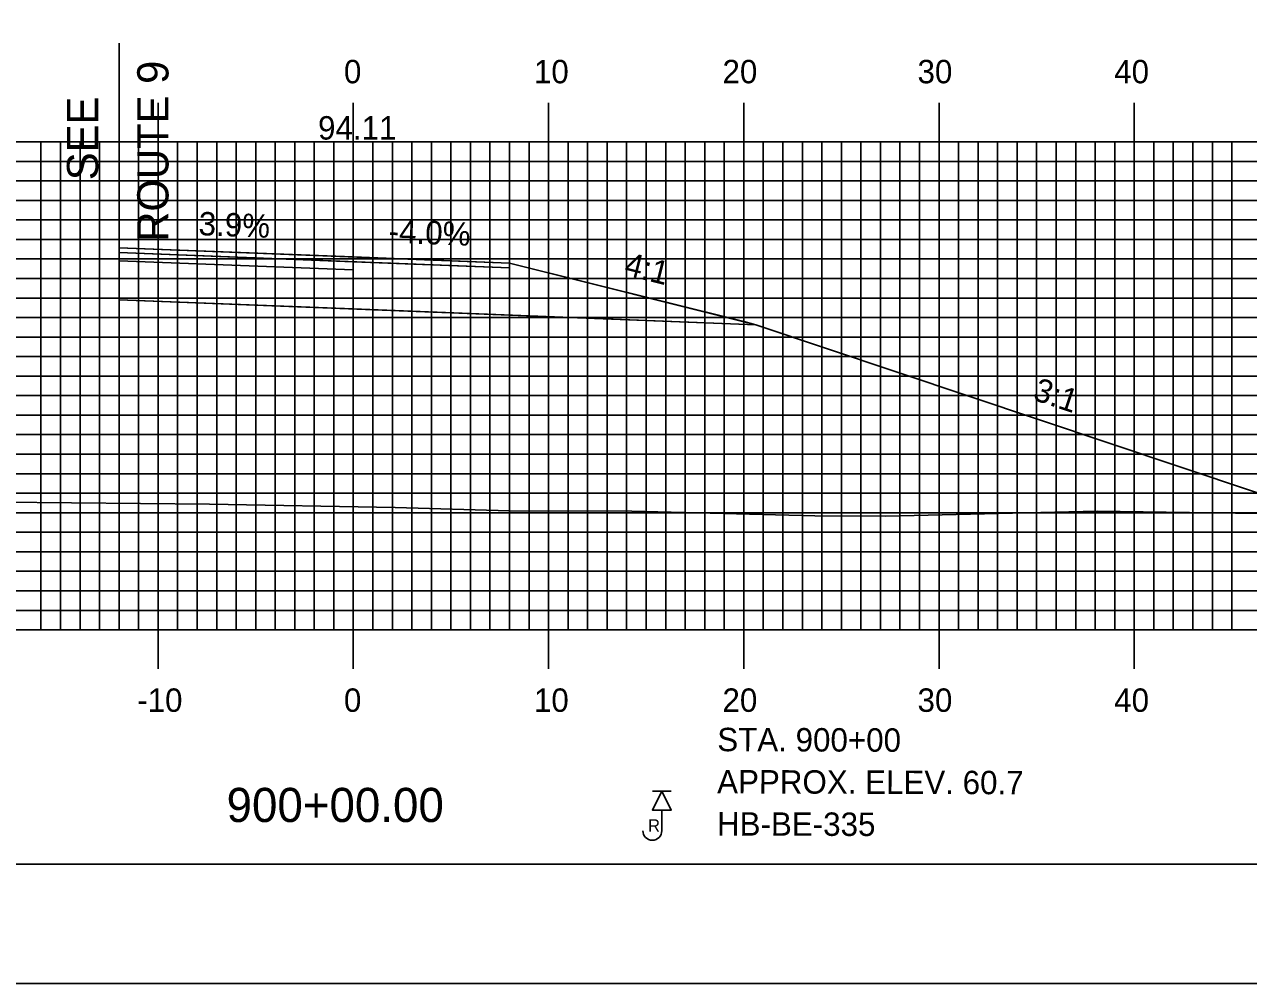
# Model space of a CAD drawing. Extents: x 856323 to 856666, y 364765 to 364985.
# Drawn here: x 856471.9 to 856534.6, y 364765.2 to 364814.3 of the extents above; entities that cross this region are included whole.
import ezdxf

# ---------------------------------------------------------------- set-up
doc = ezdxf.new("R2010")
doc.units = 0
for name, color, linetype in [('ANNOTATION', 7, 'Continuous'), ('BORDER', 7, 'Continuous'), ('BORING - REFUSAL', 7, 'Continuous'), ('D_Roadway_Centerline', 7, 'Continuous'), ('D_Roadway_Centerline_Text', 7, 'Continuous'), ('D_Roadway_Edge_Shoulder', 7, 'Continuous'), ('D_Roadway_Edge_TW', 7, 'Continuous'), ('D_Roadway_Pavement', 7, 'Continuous'), ('D_Roadway_SlopeLines', 7, 'Continuous'), ('D_Roadway_SubGrade', 7, 'Continuous'), ('H_V ANNOTATION', 7, 'Continuous'), ('MAJOR', 7, 'Continuous'), ('MINOR', 7, 'Continuous'), ('PLOT BOUNDARY', 7, 'Continuous'), ('S_Roadway_Centerline', 7, 'Continuous')]:
    doc.layers.add(name, color=color, linetype=linetype)

msp = doc.modelspace()

# ---------------------------------------------------------------- linework, layer by layer
at = {"layer": 'BORDER'}
msp.add_lwpolyline([(856339.168, 364771.302), (856659.168, 364771.302), (856659.168, 364981.302), (856339.168, 364981.302)], close=True, dxfattribs=at)
at = {"layer": 'BORING - REFUSAL'}
for p, q in [((856505.048, 364775.03), (856504.089, 364775.03)), ((856504.568, 364774.07), (856504.568, 364773.011))]:
    msp.add_line(p, q, dxfattribs=at)
msp.add_lwpolyline([(856504.568, 364775.03), (856505.048, 364774.07), (856504.089, 364774.07)], close=True, dxfattribs=at)
msp.add_arc((856504.083, 364773.011), 0.485, 180, 0, dxfattribs=at)
at = {"layer": 'D_Roadway_Centerline'}
msp.add_lwpolyline([(856476.768, 364802.881), (856476.768, 364802.881), (856488.768, 364802.411), (856496.768, 364802.091), (856508.768, 364799.091), (856509.389, 364798.935), (856538.439, 364789.201), (856538.441, 364789.2)], dxfattribs=at)
at = {"layer": 'D_Roadway_Edge_Shoulder'}
for points in [[(856476.768, 364802.881), (856496.768, 364802.091), (856496.768, 364801.841), (856476.768, 364802.631)], [(856476.768, 364802.881), (856496.768, 364802.091), (856496.768, 364801.841), (856476.768, 364802.631)], [(856476.768, 364802.881), (856496.768, 364802.091), (856496.768, 364801.841), (856476.768, 364802.631)], [(856476.768, 364802.881), (856496.768, 364802.091), (856496.768, 364801.841), (856476.768, 364802.631)], [(856476.768, 364802.881), (856496.768, 364802.091), (856496.768, 364801.841), (856476.768, 364802.631)], [(856476.768, 364802.881), (856496.768, 364802.091), (856496.768, 364801.841), (856476.768, 364802.631)], [(856488.768, 364802.411), (856496.768, 364802.091), (856496.768, 364801.841), (856488.768, 364802.161)]]:
    msp.add_lwpolyline(points, close=True, dxfattribs=at)
at = {"layer": 'D_Roadway_Edge_TW'}
msp.add_lwpolyline([(856476.768, 364802.881), (856476.768, 364802.631)], dxfattribs=at)
msp.add_lwpolyline([(856476.768, 364802.881), (856488.768, 364802.411), (856488.768, 364802.161), (856476.768, 364802.631)], close=True, dxfattribs=at)
msp.add_lwpolyline([(856476.768, 364802.881), (856488.768, 364802.411), (856488.768, 364802.161), (856476.768, 364802.631)], close=True, dxfattribs=at)
at = {"layer": 'D_Roadway_Pavement'}
msp.add_lwpolyline([(856476.768, 364802.631), (856488.768, 364802.161), (856488.768, 364801.744), (856476.768, 364802.214)], close=True, dxfattribs=at)
msp.add_lwpolyline([(856476.768, 364802.631), (856488.768, 364802.161), (856488.768, 364801.744), (856476.768, 364802.214)], close=True, dxfattribs=at)
for points in [[(856476.768, 364802.631), (856476.768, 364802.214)], [(856476.768, 364802.631), (856476.768, 364802.214)], [(856476.768, 364802.631), (856476.768, 364802.214)], [(856476.768, 364802.631), (856476.768, 364802.214)], [(856476.768, 364802.631), (856476.768, 364802.214)], [(856476.768, 364802.631), (856476.768, 364802.214)], [(856476.768, 364802.631), (856476.768, 364802.214)], [(856488.768, 364802.161), (856488.768, 364801.744)], [(856488.768, 364802.161), (856488.768, 364801.744)], [(856488.768, 364802.161), (856488.768, 364801.744)], [(856488.768, 364802.161), (856488.768, 364801.744)], [(856488.768, 364802.161), (856488.768, 364801.744)], [(856488.768, 364802.161), (856488.768, 364801.744)], [(856488.768, 364802.161), (856488.768, 364801.744)], [(856488.768, 364802.161), (856488.768, 364801.744)]]:
    msp.add_lwpolyline(points, dxfattribs=at)
at = {"layer": 'D_Roadway_SlopeLines'}
msp.add_lwpolyline([(856496.768, 364802.091), (856509.389, 364798.935), (856538.441, 364789.2)], dxfattribs=at)
at = {"layer": 'D_Roadway_SubGrade'}
msp.add_line((856476.768, 364813.354), (856476.768, 364800.214), dxfattribs=at)
for points in [[(856476.768, 364800.214), (856509.389, 364798.935), (856496.768, 364802.091), (856496.768, 364801.841), (856476.768, 364802.631)], [(856476.768, 364802.214), (856476.768, 364802.631), (856496.768, 364801.841), (856496.768, 364802.091), (856509.389, 364798.935), (856476.768, 364800.214)], [(856476.768, 364802.214), (856476.768, 364802.631), (856496.768, 364801.841), (856496.768, 364802.091), (856509.389, 364798.935), (856476.768, 364800.214)], [(856476.768, 364802.214), (856476.768, 364802.631), (856496.768, 364801.841), (856496.768, 364802.091), (856509.389, 364798.935), (856476.768, 364800.214)], [(856476.768, 364802.214), (856476.768, 364802.631), (856496.768, 364801.841), (856496.768, 364802.091), (856509.389, 364798.935), (856476.768, 364800.214)], [(856476.768, 364802.214), (856476.768, 364802.631), (856496.768, 364801.841), (856496.768, 364802.091), (856509.389, 364798.935), (856476.768, 364800.214)], [(856496.768, 364801.841), (856476.768, 364802.631), (856476.768, 364802.214), (856476.768, 364800.214), (856509.389, 364798.935), (856496.768, 364802.091)], [(856496.768, 364801.841), (856476.768, 364802.631), (856476.768, 364802.214), (856476.768, 364800.214), (856509.389, 364798.935), (856496.768, 364802.091)], [(856476.768, 364802.214), (856488.768, 364801.744), (856488.768, 364799.744), (856476.768, 364800.214)], [(856476.768, 364802.214), (856488.768, 364801.744), (856488.768, 364799.744), (856476.768, 364800.214)], [(856488.768, 364801.744), (856488.768, 364802.161), (856496.768, 364801.841), (856496.768, 364802.091), (856509.389, 364798.935), (856488.768, 364799.744)], [(856488.768, 364801.744), (856488.768, 364802.161), (856496.768, 364801.841), (856496.768, 364802.091), (856509.389, 364798.935), (856488.768, 364799.744)], [(856488.768, 364799.744), (856509.389, 364798.935), (856496.768, 364802.091), (856496.768, 364801.841), (856488.768, 364802.161), (856488.768, 364801.744)]]:
    msp.add_lwpolyline(points, close=True, dxfattribs=at)
msp.add_lwpolyline([(856476.768, 364802.214), (856476.768, 364800.214)], dxfattribs=at)
at = {"layer": 'MAJOR'}
for p, q in [((856478.768, 364810.306), (856478.768, 364808.302)), ((856488.768, 364810.306), (856488.768, 364808.302)), ((856498.768, 364810.306), (856498.768, 364808.302)), ((856508.768, 364810.306), (856508.768, 364808.302)), ((856518.768, 364810.306), (856518.768, 364808.302)), ((856528.768, 364810.306), (856528.768, 364808.302)), ((856348.768, 364808.302), (856628.768, 364808.302)), ((856348.768, 364808.302), (856628.768, 364808.302)), ((856478.768, 364783.302), (856478.768, 364808.302)), ((856488.768, 364783.302), (856488.768, 364808.302)), ((856498.768, 364783.302), (856498.768, 364808.302)), ((856508.768, 364783.302), (856508.768, 364808.302)), ((856518.768, 364783.302), (856518.768, 364808.302)), ((856528.768, 364783.302), (856528.768, 364808.302)), ((856348.768, 364803.302), (856628.768, 364803.302)), ((856348.768, 364798.302), (856628.768, 364798.302)), ((856348.768, 364793.302), (856628.768, 364793.302)), ((856348.768, 364788.302), (856628.768, 364788.302)), ((856348.768, 364783.302), (856628.768, 364783.302)), ((856348.768, 364783.302), (856628.768, 364783.302)), ((856478.768, 364781.298), (856478.768, 364783.302)), ((856488.768, 364781.298), (856488.768, 364783.302)), ((856498.768, 364781.298), (856498.768, 364783.302)), ((856508.768, 364781.298), (856508.768, 364783.302)), ((856518.768, 364781.298), (856518.768, 364783.302)), ((856528.768, 364781.298), (856528.768, 364783.302))]:
    msp.add_line(p, q, dxfattribs=at)
at = {"layer": 'MINOR'}
for p, q in [((856472.768, 364783.302), (856472.768, 364808.302)), ((856473.768, 364783.302), (856473.768, 364808.302)), ((856474.768, 364783.302), (856474.768, 364808.302)), ((856475.768, 364783.302), (856475.768, 364808.302)), ((856476.768, 364783.302), (856476.768, 364808.302)), ((856477.768, 364783.302), (856477.768, 364808.302)), ((856479.768, 364783.302), (856479.768, 364808.302)), ((856480.768, 364783.302), (856480.768, 364808.302)), ((856481.768, 364783.302), (856481.768, 364808.302)), ((856482.768, 364783.302), (856482.768, 364808.302)), ((856483.768, 364783.302), (856483.768, 364808.302)), ((856484.768, 364783.302), (856484.768, 364808.302)), ((856485.768, 364783.302), (856485.768, 364808.302)), ((856486.768, 364783.302), (856486.768, 364808.302)), ((856487.768, 364783.302), (856487.768, 364808.302)), ((856489.768, 364783.302), (856489.768, 364808.302)), ((856490.768, 364783.302), (856490.768, 364808.302)), ((856491.768, 364783.302), (856491.768, 364808.302)), ((856492.768, 364783.302), (856492.768, 364808.302)), ((856493.768, 364783.302), (856493.768, 364808.302)), ((856494.768, 364783.302), (856494.768, 364808.302)), ((856495.768, 364783.302), (856495.768, 364808.302)), ((856496.768, 364783.302), (856496.768, 364808.302)), ((856497.768, 364783.302), (856497.768, 364808.302)), ((856499.768, 364783.302), (856499.768, 364808.302)), ((856500.768, 364783.302), (856500.768, 364808.302)), ((856501.768, 364783.302), (856501.768, 364808.302)), ((856502.768, 364783.302), (856502.768, 364808.302)), ((856503.768, 364783.302), (856503.768, 364808.302)), ((856504.768, 364783.302), (856504.768, 364808.302)), ((856505.768, 364783.302), (856505.768, 364808.302)), ((856506.768, 364783.302), (856506.768, 364808.302)), ((856507.768, 364783.302), (856507.768, 364808.302)), ((856509.768, 364783.302), (856509.768, 364808.302)), ((856510.768, 364783.302), (856510.768, 364808.302)), ((856511.768, 364783.302), (856511.768, 364808.302)), ((856512.768, 364783.302), (856512.768, 364808.302)), ((856513.768, 364783.302), (856513.768, 364808.302)), ((856514.768, 364783.302), (856514.768, 364808.302)), ((856515.768, 364783.302), (856515.768, 364808.302)), ((856516.768, 364783.302), (856516.768, 364808.302)), ((856517.768, 364783.302), (856517.768, 364808.302)), ((856519.768, 364783.302), (856519.768, 364808.302)), ((856520.768, 364783.302), (856520.768, 364808.302)), ((856521.768, 364783.302), (856521.768, 364808.302)), ((856522.768, 364783.302), (856522.768, 364808.302)), ((856523.768, 364783.302), (856523.768, 364808.302)), ((856524.768, 364783.302), (856524.768, 364808.302)), ((856525.768, 364783.302), (856525.768, 364808.302)), ((856526.768, 364783.302), (856526.768, 364808.302)), ((856527.768, 364783.302), (856527.768, 364808.302)), ((856529.768, 364783.302), (856529.768, 364808.302)), ((856530.768, 364783.302), (856530.768, 364808.302)), ((856531.768, 364783.302), (856531.768, 364808.302)), ((856532.768, 364783.302), (856532.768, 364808.302)), ((856533.768, 364783.302), (856533.768, 364808.302)), ((856348.768, 364807.302), (856628.768, 364807.302)), ((856348.768, 364806.302), (856628.768, 364806.302)), ((856348.768, 364805.302), (856628.768, 364805.302)), ((856348.768, 364804.302), (856628.768, 364804.302)), ((856348.768, 364802.302), (856628.768, 364802.302)), ((856348.768, 364801.302), (856628.768, 364801.302)), ((856348.768, 364800.302), (856628.768, 364800.302)), ((856348.768, 364799.302), (856628.768, 364799.302)), ((856348.768, 364797.302), (856628.768, 364797.302)), ((856348.768, 364796.302), (856628.768, 364796.302)), ((856348.768, 364795.302), (856628.768, 364795.302)), ((856348.768, 364794.302), (856628.768, 364794.302)), ((856348.768, 364792.302), (856628.768, 364792.302)), ((856348.768, 364791.302), (856628.768, 364791.302)), ((856348.768, 364790.302), (856628.768, 364790.302)), ((856348.768, 364789.302), (856628.768, 364789.302)), ((856348.768, 364787.302), (856628.768, 364787.302)), ((856348.768, 364786.302), (856628.768, 364786.302)), ((856348.768, 364785.302), (856628.768, 364785.302)), ((856348.768, 364784.302), (856628.768, 364784.302))]:
    msp.add_line(p, q, dxfattribs=at)
at = {"layer": 'PLOT BOUNDARY'}
msp.add_lwpolyline([(856322.982, 364765.184), (856662.982, 364765.184), (856662.982, 364985.184), (856322.982, 364985.184)], close=True, dxfattribs=at)
at = {"layer": 'S_Roadway_Centerline'}
msp.add_lwpolyline([(856467.245, 364789.883), (856481.397, 364789.741), (856490.903, 364789.576), (856496.772, 364789.408), (856503.027, 364789.391), (856512.402, 364789.138), (856516.046, 364789.126), (856526.862, 364789.385), (856535.128, 364789.259), (856545.068, 364789.082), (856550.824, 364789.019), (856554.531, 364789.035), (856563.493, 364788.873), (856574.574, 364788.764), (856575.241, 364788.768), (856576.228, 364788.745), (856592.678, 364788.737), (856598.386, 364788.819), (856608.798, 364788.494), (856611.234, 364788.396), (856612.656, 364788.381), (856621.756, 364788.461), (856628.768, 364788.505)], dxfattribs=at)

# ---------------------------------------------------------------- texts
at = {"layer": 'ANNOTATION'}
for s, height, rotation, p in [('ROUTE 9', 1.6, 90, (856479.299, 364803.187)), ('SEE', 1.6, 90, (856475.699, 364806.337)), ('3.9%', 1.2, 357.75472, (856480.826, 364803.524)), ('-4.0%', 1.2, 357.70939, (856490.56, 364803.141)), ('4:1', 1.2, 345.96376, (856502.585, 364801.498)), ('3:1', 1.2, 341.47345, (856523.521, 364795.109))]:
    msp.add_text(s, height=height, rotation=rotation, dxfattribs=at).set_placement(p)
at = {"layer": 'BORING - REFUSAL'}
for s, p in [('STA. 900+00', (856507.408, 364777.086)), ('APPROX. ELEV. 60.7', (856507.401, 364774.926)), ('HB-BE-335', (856507.394, 364772.766))]:
    msp.add_text(s, height=1.2, rotation=359.81416, dxfattribs=at).set_placement(p)
msp.add_text('R', height=0.64, dxfattribs=at).set_placement((856503.86, 364772.956))
at = {"layer": 'D_Roadway_Centerline_Text'}
msp.add_text('94.11', height=1.2, dxfattribs=at).set_placement((856486.96, 364808.419))
at = {"layer": 'H_V ANNOTATION'}
for s, height, p in [('0', 1.2, (856488.287, 364811.302)), ('10', 1.2, (856498.019, 364811.302)), ('20', 1.2, (856507.676, 364811.302)), ('30', 1.2, (856517.666, 364811.302)), ('40', 1.2, (856527.741, 364811.302)), ('-10', 1.2, (856477.698, 364779.102)), ('0', 1.2, (856488.287, 364779.102)), ('10', 1.2, (856498.019, 364779.102)), ('20', 1.2, (856507.676, 364779.102)), ('30', 1.2, (856517.666, 364779.102)), ('40', 1.2, (856527.741, 364779.102)), ('900+00.00', 1.75, (856482.276, 364773.458))]:
    msp.add_text(s, height=height, dxfattribs=at).set_placement(p)

doc.saveas('drawing.dxf')
